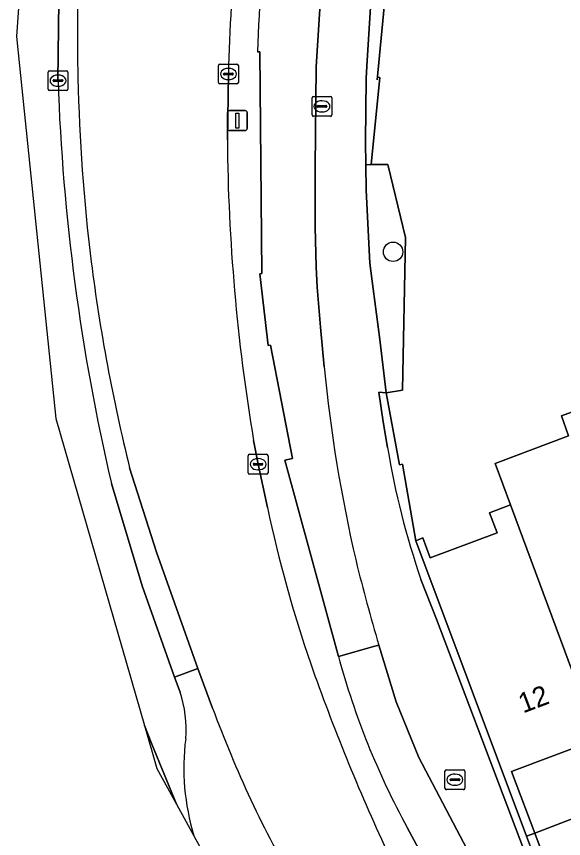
# Model space of a CAD drawing. Extents: x 160663 to 161506, y 382245 to 383291.
# Drawn here: x 160662.59 to 160690.09, y 383134.14 to 383175.45 of the extents above; entities that cross this region are included whole.
import ezdxf

# ---------------------------------------------------------------- set-up
doc = ezdxf.new("R2010")
doc.units = 0
for name, color, linetype in [('IMGEO_Berm_gesloten', 7, 'Continuous'), ('IMGEO_Berm_open', 7, 'Continuous'), ('IMGEO_Boom', 7, 'Continuous'), ('IMGEO_Erf', 7, 'Continuous'), ('IMGEO_Fietspad_gesloten', 7, 'Continuous'), ('IMGEO_Fietspad_open', 7, 'Continuous'), ('IMGEO_Groenvoorziening', 7, 'Continuous'), ('IMGEO_Haag', 7, 'Continuous'), ('IMGEO_Kolk', 7, 'Continuous'), ('IMGEO_Lichtmast', 7, 'Continuous'), ('IMGEO_Muur', 7, 'Continuous'), ('IMGEO_Pand', 7, 'Continuous'), ('IMGEO_Pand_nummerreeks', 7, 'Continuous'), ('IMGEO_Pand_overbouw', 7, 'Continuous'), ('IMGEO_Rijbaan_lokaal_gesloten', 7, 'Continuous'), ('IMGEO_Rioolput', 7, 'Continuous'), ('IMGEO_Voetpad_open', 7, 'Continuous')]:
    doc.layers.add(name, color=color, linetype=linetype)

msp = doc.modelspace()

# ---------------------------------------------------------------- linework, layer by layer
at = {"layer": 'IMGEO_Berm_gesloten'}
for points in [[(160665.999, 383192.975), (160665.276, 383186.827), (160664.748, 383178.894), (160664.679, 383172.227)], [(160667.367, 383151.979), (160668.909, 383146.839), (160670.541, 383142.243), (160671.716, 383142.678), (160669.629, 383148.526), (160668.281, 383152.765)]]:
    msp.add_lwpolyline(points, dxfattribs=at)
for centre, radius, start, end in [((160766.24, 383174.55), 100.581, 160.36227, 181.25641), ((160754.17, 383174.111), 88.504, 181.14338, 187.13117), ((160769.093, 383175.786), 104.474, 181.95215, 193.17189), ((160754.088, 383174.12), 88.424, 187.14324, 193.97516)]:
    msp.add_arc(centre, radius, start, end, dxfattribs=at)
at = {"layer": 'IMGEO_Berm_open'}
for points in [[(160676.079, 383153.149), (160676.474, 383153.238), (160675.361, 383158.93), (160675.236, 383158.916), (160674.821, 383162.521), (160674.928, 383162.528), (160674.82, 383173.67), (160674.699, 383173.666)], [(160673.244, 383172.558), (160673.191, 383169.258)], [(160674.508, 383154.138), (160674.736, 383152.95), (160675.211, 383150.768)], [(160678.773, 383143.293), (160676.079, 383153.149)], [(160686.25, 383127.523), (160683.772, 383131.833), (160682.228, 383134.688)]]:
    msp.add_lwpolyline(points, dxfattribs=at)
for centre, radius, start, end in [((160749.666, 383171.084), 76.436, 168.75951, 178.89467), ((160756.054, 383170.693), 81.409, 172.7867, 177.90714), ((160770.077, 383170.08), 96.889, 180.48592, 189.47024), ((160739.82, 383164.449), 66.042, 191.95555, 199.0226), ((160717.456, 383153.829), 40.092, 195.2353, 208.5166), ((160774.65, 383176.997), 103.061, 199.30669, 204.94851)]:
    msp.add_arc(centre, radius, start, end, dxfattribs=at)
at = {"layer": 'IMGEO_Boom'}
msp.add_circle((160681.522, 383163.624), 0.489, dxfattribs=at)
at = {"layer": 'IMGEO_Erf'}
msp.add_lwpolyline([(160681.165, 383176.816), (160680.714, 383172.272), (160680.732, 383172.404), (160680.853, 383172.385), (160680.413, 383168.005), (160681.264, 383168.017), (160682.139, 383164.35), (160681.99, 383156.668), (160681.179, 383156.533), (160681.848, 383152.917), (160681.993, 383152.948), (160682.661, 383149.105), (160683.014, 383149.243), (160683.39, 383148.241), (160686.746, 383149.5), (160686.367, 383150.501), (160687.427, 383150.902), (160686.655, 383152.982), (160690.339, 383154.37), (160689.98, 383155.388), (160691.046, 383155.764)], dxfattribs=at)
at = {"layer": 'IMGEO_Fietspad_gesloten'}
for points in [[(160693.798, 383117.07), (160693.112, 383118.673), (160689.259, 383126.716), (160688.071, 383128.53), (160685.926, 383132.285), (160682.818, 383138.215), (160681.684, 383141.007), (160680.807, 383143.865), (160680.607, 383143.809), (160678.773, 383143.293)], [(160682.228, 383134.688), (160683.772, 383131.833), (160686.25, 383127.523), (160688.317, 383124.05), (160688.871, 383123.049)]]:
    msp.add_lwpolyline(points, dxfattribs=at)
msp.add_arc((160717.456, 383153.829), 40.092, 195.2353, 208.5166, dxfattribs=at)
at = {"layer": 'IMGEO_Fietspad_open'}
for points in [[(160678.062, 383157.847), (160677.872, 383159.844), (160677.706, 383161.844), (160677.655, 383162.864), (160677.604, 383164.862), (160677.598, 383167.868), (160677.66, 383172.913), (160677.907, 383176.899)], [(160674.699, 383173.666), (160674.82, 383173.67), (160674.928, 383162.528), (160674.821, 383162.521), (160675.236, 383158.916), (160675.361, 383158.93), (160676.474, 383153.238), (160676.079, 383153.149), (160678.773, 383143.293), (160680.607, 383143.809), (160680.807, 383143.865)]]:
    msp.add_lwpolyline(points, dxfattribs=at)
for centre, radius, start, end in [((160756.054, 383170.693), 81.409, 172.7867, 177.90714), ((160752.54, 383165.023), 74.822, 185.50344, 193.08214), ((160765.977, 383169.29), 88.884, 193.80114, 196.62181)]:
    msp.add_arc(centre, radius, start, end, dxfattribs=at)
at = {"layer": 'IMGEO_Groenvoorziening'}
for points in [[(160680.413, 383176.477), (160680.208, 383172.951), (160680.177, 383172.339), (160680.133, 383169.162), (160680.153, 383168.001), (160680.413, 383168.005), (160680.853, 383172.385), (160680.732, 383172.404), (160680.714, 383172.272), (160681.165, 383176.816)], [(160694.878, 383127.414), (160694.597, 383127.794), (160694.687, 383127.874), (160694.639, 383127.986), (160694.165, 383127.567), (160693.585, 383126.77), (160693.086, 383126.386), (160692.418, 383126.118), (160691.581, 383126.061), (160689.892, 383130.523), (160689.656, 383130.434), (160689.45, 383130.983), (160688.877, 383132.514), (160688.225, 383134.254), (160682.661, 383149.105), (160681.993, 383152.948), (160681.848, 383152.917), (160681.179, 383156.533), (160680.804, 383156.569), (160681.025, 383155.081), (160681.247, 383153.783)], [(160682.924, 383147.162), (160683.705, 383145.169), (160689.33, 383130.312), (160690.049, 383128.413), (160691.131, 383125.556)], [(160672.451, 383140.698), (160671.716, 383142.678), (160670.541, 383142.243), (160670.815, 383141.499)], [(160692.952, 383133.223), (160692.787, 383135.987), (160690.388, 383135.074), (160688.645, 383134.411), (160689.325, 383132.618), (160689.862, 383131.202), (160690.091, 383130.597), (160689.892, 383130.523), (160691.581, 383126.061), (160692.418, 383126.118), (160693.086, 383126.386), (160693.585, 383126.77), (160694.165, 383127.567), (160694.639, 383127.986), (160693.626, 383130.337)], [(160671.51, 383134.28), (160674.846, 383128.19)]]:
    msp.add_lwpolyline(points, dxfattribs=at)
msp.add_lwpolyline([(160681.179, 383156.533), (160681.99, 383156.668), (160682.139, 383164.35), (160681.264, 383168.017), (160680.413, 383168.005), (160680.153, 383168.001), (160680.176, 383166.719), (160680.355, 383163.046), (160680.525, 383161.77), (160680.849, 383159.223)], close=True, dxfattribs=at)
for centre, radius, start, end in [((160721.286, 383160.401), 40.582, 189.386, 199.0405), ((160665.192, 383139.633), 5.925, 355.3599, 18.3545), ((160727.086, 383160.771), 58.205, 200.17318, 210.00906), ((160682.695, 383137.682), 11.691, 172.7671, 196.9178)]:
    msp.add_arc(centre, radius, start, end, dxfattribs=at)
at = {"layer": 'IMGEO_Haag'}
for points in [[(160680.413, 383176.477), (160680.208, 383172.951), (160680.177, 383172.339), (160680.133, 383169.162), (160680.153, 383168.001), (160680.413, 383168.005), (160680.853, 383172.385), (160680.732, 383172.404), (160680.714, 383172.272), (160681.165, 383176.816)], [(160694.878, 383127.414), (160694.597, 383127.794), (160694.687, 383127.874), (160694.639, 383127.986), (160694.165, 383127.567), (160693.585, 383126.77), (160693.086, 383126.386), (160692.418, 383126.118), (160691.581, 383126.061), (160689.892, 383130.523), (160689.656, 383130.434), (160689.45, 383130.983), (160688.877, 383132.514), (160688.225, 383134.254), (160682.661, 383149.105), (160681.993, 383152.948), (160681.848, 383152.917), (160681.179, 383156.533), (160680.804, 383156.569), (160681.025, 383155.081), (160681.247, 383153.783)], [(160682.924, 383147.162), (160683.705, 383145.169), (160689.33, 383130.312), (160690.049, 383128.413), (160691.131, 383125.556)]]:
    msp.add_lwpolyline(points, dxfattribs=at)
msp.add_arc((160721.286, 383160.401), 40.582, 189.386, 199.0405, dxfattribs=at)
at = {"layer": 'IMGEO_Kolk'}
for p, q in [((160664.255, 383172.724), (160665.107, 383172.724)), ((160672.744, 383172.132), (160672.744, 383172.984)), ((160672.819, 383173.058), (160673.671, 383173.058)), ((160673.232, 383172.838), (160673.257, 383172.838)), ((160673.745, 383172.984), (160673.745, 383172.132)), ((160664.18, 383171.798), (160664.18, 383172.65)), ((160664.482, 383172.267), (160664.88, 383172.267)), ((160664.668, 383172.504), (160664.693, 383172.504)), ((160665.181, 383172.65), (160665.181, 383171.798)), ((160673.003, 383172.552), (160673.003, 383172.564)), ((160673.441, 383172.515), (160673.043, 383172.515)), ((160673.046, 383172.601), (160673.444, 383172.601)), ((160673.255, 383172.278), (160673.23, 383172.278)), ((160673.487, 383172.564), (160673.487, 383172.552)), ((160664.439, 383172.218), (160664.439, 383172.23)), ((160664.877, 383172.181), (160664.479, 383172.181)), ((160664.691, 383171.944), (160664.666, 383171.944)), ((160664.923, 383172.23), (160664.923, 383172.218)), ((160673.671, 383172.058), (160672.819, 383172.058)), ((160665.107, 383171.724), (160664.255, 383171.724)), ((160674.236, 383152.525), (160674.236, 383153.377)), ((160674.311, 383153.451), (160675.163, 383153.451)), ((160675.237, 383153.377), (160675.237, 383152.525)), ((160674.495, 383152.945), (160674.495, 383152.957)), ((160674.933, 383152.908), (160674.535, 383152.908)), ((160674.538, 383152.994), (160674.936, 383152.994)), ((160674.724, 383153.231), (160674.749, 383153.231)), ((160674.979, 383152.957), (160674.979, 383152.945)), ((160675.163, 383152.451), (160674.311, 383152.451)), ((160674.747, 383152.671), (160674.722, 383152.671))]:
    msp.add_line(p, q, dxfattribs=at)
for points in [[(160664.255, 383172.724), (160665.107, 383172.724)], [(160672.744, 383172.132), (160672.744, 383172.984)], [(160672.819, 383173.058), (160673.671, 383173.058)], [(160673.745, 383172.984), (160673.745, 383172.132)], [(160664.18, 383171.798), (160664.18, 383172.65)], [(160665.181, 383172.65), (160665.181, 383171.798)], [(160673.671, 383172.058), (160672.819, 383172.058)], [(160665.107, 383171.724), (160664.255, 383171.724)], [(160674.236, 383152.525), (160674.236, 383153.377)], [(160674.311, 383153.451), (160675.163, 383153.451)], [(160675.237, 383153.377), (160675.237, 383152.525)], [(160675.163, 383152.451), (160674.311, 383152.451)]]:
    msp.add_lwpolyline(points, dxfattribs=at)
for centre, radius, start, end in [((160664.257, 383172.648), 0.0765, 91.552, 178.448), ((160664.257, 383172.648), 0.0765, 91.552, 178.448), ((160665.105, 383172.648), 0.0765, 1.552, 88.448), ((160665.105, 383172.648), 0.0765, 1.552, 88.448), ((160672.821, 383172.982), 0.0765, 91.552, 178.448), ((160672.821, 383172.982), 0.0765, 91.552, 178.448), ((160673.669, 383172.982), 0.0765, 1.552, 88.448), ((160673.669, 383172.982), 0.0765, 1.552, 88.448), ((160664.479, 383172.227), 0.0403, 85.8775, 175.7526), ((160664.884, 383172.229), 0.0386, 1.7309, 96.639), ((160673.043, 383172.561), 0.0403, 85.8775, 175.7526), ((160673.04, 383172.551), 0.0366, 178.938, 274.7102), ((160673.444, 383172.558), 0.043, 264.8664, 352.4533), ((160673.448, 383172.563), 0.0386, 1.7309, 96.639), ((160664.476, 383172.217), 0.0366, 178.938, 274.7102), ((160664.88, 383172.224), 0.043, 264.8664, 352.4533), ((160672.821, 383172.134), 0.0765, 181.552, 268.448), ((160672.821, 383172.134), 0.0765, 181.552, 268.448), ((160673.669, 383172.134), 0.0765, 271.552, 358.448), ((160673.669, 383172.134), 0.0765, 271.552, 358.448), ((160664.257, 383171.8), 0.0765, 181.552, 268.448), ((160664.257, 383171.8), 0.0765, 181.552, 268.448), ((160665.105, 383171.8), 0.0765, 271.552, 358.448), ((160665.105, 383171.8), 0.0765, 271.552, 358.448), ((160674.313, 383153.375), 0.0765, 91.552, 178.448), ((160674.313, 383153.375), 0.0765, 91.552, 178.448), ((160675.161, 383153.375), 0.0765, 1.552, 88.448), ((160675.161, 383153.375), 0.0765, 1.552, 88.448), ((160674.535, 383152.954), 0.0403, 85.8775, 175.7526), ((160674.532, 383152.944), 0.0366, 178.938, 274.7102), ((160674.936, 383152.951), 0.043, 264.8664, 352.4533), ((160674.94, 383152.956), 0.0386, 1.7309, 96.639), ((160674.313, 383152.527), 0.0765, 181.552, 268.448), ((160674.313, 383152.527), 0.0765, 181.552, 268.448), ((160675.161, 383152.527), 0.0765, 271.552, 358.448), ((160675.161, 383152.527), 0.0765, 271.552, 358.448)]:
    msp.add_arc(centre, radius, start, end, dxfattribs=at)
for centre, major_axis, ratio, start_param, end_param in [((160673.231, 383172.558), (-0.387, 0.002), 0.722429, 4.712389, 7.853982), ((160673.256, 383172.558), (-0.39, 0.002), 0.717154, 1.570796, 4.712389), ((160664.667, 383172.224), (-0.387, 0.002), 0.722429, 4.712389, 7.853982), ((160664.692, 383172.224), (-0.39, 0.002), 0.717154, 1.570796, 4.712389), ((160674.723, 383152.951), (-0.387, 0.002), 0.722429, 4.712389, 7.853982), ((160674.748, 383152.951), (-0.39, 0.002), 0.717154, 1.570796, 4.712389)]:
    msp.add_ellipse(centre, major_axis=major_axis, ratio=ratio, start_param=start_param, end_param=end_param, dxfattribs=at)
at = {"layer": 'IMGEO_Lichtmast'}
for p, q in [((160673.199, 383169.819), (160673.199, 383170.619)), ((160673.199, 383170.619), (160673.199, 383169.819)), ((160673.299, 383170.719), (160674.089, 383170.719)), ((160674.089, 383170.719), (160673.299, 383170.719)), ((160674.189, 383170.619), (160674.189, 383169.819)), ((160674.189, 383169.819), (160674.189, 383170.619)), ((160674.089, 383169.719), (160673.299, 383169.719)), ((160673.299, 383169.719), (160674.089, 383169.719))]:
    msp.add_line(p, q, dxfattribs=at)
msp.add_lwpolyline([(160673.619, 383170.594), (160673.769, 383170.594), (160673.769, 383169.844), (160673.619, 383169.844), (160673.619, 383170.594)], dxfattribs=at)
for centre, start, end in [((160673.299, 383170.619), 90, 180), ((160673.299, 383170.619), 90, 180), ((160674.089, 383170.619), 0, 90), ((160674.089, 383170.619), 360, 90), ((160673.299, 383169.819), 180, 270), ((160673.299, 383169.819), 180, 270), ((160674.089, 383169.819), 270, 0), ((160674.089, 383169.819), 270, 0)]:
    msp.add_arc(centre, 0.1, start, end, dxfattribs=at)
at = {"layer": 'IMGEO_Muur'}
msp.add_lwpolyline([(160687.718, 383202.423), (160686.074, 383198.261), (160686.135, 383198.38), (160686.238, 383198.331), (160684.578, 383194.06), (160684.637, 383194.186), (160684.746, 383194.124), (160683.252, 383189.796), (160683.308, 383189.923), (160683.42, 383189.871), (160682.202, 383185.493), (160682.257, 383185.625), (160682.375, 383185.575), (160681.483, 383181.119), (160681.526, 383181.232), (160681.646, 383181.19), (160681.02, 383176.711), (160681.047, 383176.835), (160681.165, 383176.816), (160680.714, 383172.272), (160680.732, 383172.404), (160680.853, 383172.385), (160680.413, 383168.005)], dxfattribs=at)
msp.add_lwpolyline([(160689.862, 383131.202), (160689.325, 383132.618), (160688.645, 383134.411), (160688.225, 383134.254), (160688.877, 383132.514), (160689.45, 383130.983), (160689.656, 383130.434), (160689.892, 383130.523), (160690.091, 383130.597)], close=True, dxfattribs=at)
at = {"layer": 'IMGEO_Pand'}
for points in [[(160691.046, 383155.764), (160689.98, 383155.388), (160690.339, 383154.37), (160686.655, 383152.982), (160687.427, 383150.902), (160691.792, 383139.141), (160692.254, 383139.315), (160692.879, 383139.558), (160692.756, 383139.873), (160692.123, 383139.625), (160691.087, 383142.408), (160695.406, 383144.016)], [(160687.427, 383150.902), (160686.367, 383150.501), (160686.746, 383149.5), (160683.39, 383148.241), (160683.014, 383149.243), (160682.661, 383149.105), (160688.225, 383134.254), (160688.645, 383134.411), (160687.478, 383137.512), (160691.792, 383139.141)]]:
    msp.add_lwpolyline(points, close=True, dxfattribs=at)
at = {"layer": 'IMGEO_Pand_overbouw'}
msp.add_lwpolyline([(160692.672, 383138.199), (160692.254, 383139.315), (160691.792, 383139.141), (160687.478, 383137.512), (160688.645, 383134.411), (160690.388, 383135.074), (160692.787, 383135.987), (160693.411, 383136.224)], close=True, dxfattribs=at)
at = {"layer": 'IMGEO_Rijbaan_lokaal_gesloten'}
for points in [[(160687.72, 383258.106), (160688.057, 383259.324), (160689.344, 383264.684), (160688.005, 383264.811), (160677.782, 383230.912), (160664.085, 383195.806), (160662.59, 383174.443), (160662.741, 383172.971), (160664.567, 383155.247), (160669.029, 383139.828), (160669.397, 383138.878), (160670.641, 383135.865), (160671.51, 383134.28)], [(160664.679, 383172.227), (160664.748, 383178.894), (160665.276, 383186.827), (160665.999, 383192.975)], [(160673.191, 383169.258), (160673.244, 383172.558)], [(160675.211, 383150.768), (160674.736, 383152.95), (160674.508, 383154.138)], [(160668.281, 383152.765), (160669.629, 383148.526), (160671.716, 383142.678), (160672.451, 383140.698)], [(160670.815, 383141.499), (160670.541, 383142.243), (160668.909, 383146.839), (160667.367, 383151.979)], [(160669.029, 383139.828), (160669.655, 383137.666), (160670.641, 383135.865), (160669.397, 383138.878), (160669.029, 383139.828)]]:
    msp.add_lwpolyline(points, dxfattribs=at)
for centre, radius, start, end in [((160766.24, 383174.55), 100.581, 160.36227, 181.25641), ((160749.666, 383171.084), 76.436, 168.75951, 178.89467), ((160754.17, 383174.111), 88.504, 181.14338, 187.13117), ((160769.093, 383175.786), 104.474, 181.95215, 193.17189), ((160770.077, 383170.08), 96.889, 180.48592, 189.47024), ((160754.088, 383174.12), 88.424, 187.14324, 193.97516), ((160739.82, 383164.449), 66.042, 191.95555, 199.0226), ((160774.65, 383176.997), 103.061, 199.30669, 204.94851), ((160665.192, 383139.633), 5.925, 355.3599, 18.3545), ((160727.086, 383160.771), 58.205, 200.17318, 210.00906), ((160682.695, 383137.682), 11.691, 172.7671, 196.9178)]:
    msp.add_arc(centre, radius, start, end, dxfattribs=at)
at = {"layer": 'IMGEO_Rioolput'}
for p, q in [((160677.522, 383171.431), (160678.374, 383171.431)), ((160677.447, 383170.505), (160677.447, 383171.357)), ((160677.935, 383171.211), (160677.96, 383171.211)), ((160678.448, 383171.357), (160678.448, 383170.505)), ((160677.706, 383170.925), (160677.706, 383170.937)), ((160678.144, 383170.888), (160677.746, 383170.888)), ((160677.749, 383170.974), (160678.147, 383170.974)), ((160677.958, 383170.651), (160677.933, 383170.651)), ((160678.19, 383170.937), (160678.19, 383170.925)), ((160678.374, 383170.431), (160677.522, 383170.431)), ((160684.205, 383137.597), (160685.057, 383137.597)), ((160684.13, 383136.671), (160684.13, 383137.523)), ((160684.618, 383137.377), (160684.643, 383137.377)), ((160685.131, 383137.523), (160685.131, 383136.671)), ((160684.389, 383137.091), (160684.389, 383137.103)), ((160684.827, 383137.054), (160684.429, 383137.054)), ((160684.432, 383137.14), (160684.83, 383137.14)), ((160684.641, 383136.817), (160684.616, 383136.817)), ((160684.873, 383137.103), (160684.873, 383137.091)), ((160685.057, 383136.597), (160684.205, 383136.597))]:
    msp.add_line(p, q, dxfattribs=at)
for points in [[(160677.522, 383171.431), (160678.374, 383171.431)], [(160677.447, 383170.505), (160677.447, 383171.357)], [(160678.448, 383171.357), (160678.448, 383170.505)], [(160678.374, 383170.431), (160677.522, 383170.431)], [(160684.205, 383137.597), (160685.057, 383137.597)], [(160684.13, 383136.671), (160684.13, 383137.523)], [(160685.131, 383137.523), (160685.131, 383136.671)], [(160685.057, 383136.597), (160684.205, 383136.597)]]:
    msp.add_lwpolyline(points, dxfattribs=at)
for centre, radius, start, end in [((160677.524, 383171.355), 0.0765, 91.552, 178.448), ((160677.524, 383171.355), 0.0765, 91.552, 178.448), ((160678.372, 383171.355), 0.0765, 1.552, 88.448), ((160678.372, 383171.355), 0.0765, 1.552, 88.448), ((160677.746, 383170.934), 0.0403, 85.8775, 175.7526), ((160677.743, 383170.924), 0.0366, 178.938, 274.7102), ((160678.147, 383170.931), 0.043, 264.8664, 352.4533), ((160678.151, 383170.936), 0.0386, 1.7309, 96.639), ((160677.524, 383170.507), 0.0765, 181.552, 268.448), ((160677.524, 383170.507), 0.0765, 181.552, 268.448), ((160678.372, 383170.507), 0.0765, 271.552, 358.448), ((160678.372, 383170.507), 0.0765, 271.552, 358.448), ((160684.207, 383137.521), 0.0765, 91.552, 178.448), ((160684.207, 383137.521), 0.0765, 91.552, 178.448), ((160685.055, 383137.521), 0.0765, 1.552, 88.448), ((160685.055, 383137.521), 0.0765, 1.552, 88.448), ((160684.429, 383137.1), 0.0403, 85.8775, 175.7526), ((160684.426, 383137.09), 0.0366, 178.938, 274.7102), ((160684.83, 383137.097), 0.043, 264.8664, 352.4533), ((160684.834, 383137.102), 0.0386, 1.7309, 96.639), ((160684.207, 383136.673), 0.0765, 181.552, 268.448), ((160684.207, 383136.673), 0.0765, 181.552, 268.448), ((160685.055, 383136.673), 0.0765, 271.552, 358.448), ((160685.055, 383136.673), 0.0765, 271.552, 358.448)]:
    msp.add_arc(centre, radius, start, end, dxfattribs=at)
for centre, major_axis, ratio, start_param, end_param in [((160677.934, 383170.931), (-0.387, 0.002), 0.722429, 4.712389, 7.853982), ((160677.959, 383170.931), (-0.39, 0.002), 0.717154, 1.570796, 4.712389), ((160684.617, 383137.097), (-0.387, 0.002), 0.722429, 4.712389, 7.853982), ((160684.642, 383137.097), (-0.39, 0.002), 0.717154, 1.570796, 4.712389)]:
    msp.add_ellipse(centre, major_axis=major_axis, ratio=ratio, start_param=start_param, end_param=end_param, dxfattribs=at)
at = {"layer": 'IMGEO_Voetpad_open'}
for points in [[(160681.247, 383153.783), (160681.025, 383155.081), (160680.804, 383156.569), (160681.179, 383156.533), (160680.849, 383159.223), (160680.525, 383161.77), (160680.355, 383163.046), (160680.176, 383166.719), (160680.153, 383168.001), (160680.133, 383169.162), (160680.177, 383172.339), (160680.208, 383172.951), (160680.413, 383176.477), (160680.584, 383178.639), (160681.149, 383182.722), (160681.192, 383182.923)], [(160677.907, 383176.899), (160677.66, 383172.913), (160677.598, 383167.868), (160677.604, 383164.862), (160677.655, 383162.864), (160677.706, 383161.844), (160677.872, 383159.844), (160678.062, 383157.847)], [(160691.131, 383125.556), (160690.049, 383128.413), (160689.33, 383130.312), (160683.705, 383145.169), (160682.924, 383147.162)], [(160680.807, 383143.865), (160681.684, 383141.007), (160682.818, 383138.215), (160685.926, 383132.285), (160688.071, 383128.53), (160689.259, 383126.716)]]:
    msp.add_lwpolyline(points, dxfattribs=at)
msp.add_lwpolyline([(160692.672, 383138.199), (160692.254, 383139.315), (160691.792, 383139.141), (160687.478, 383137.512), (160688.645, 383134.411), (160690.388, 383135.074), (160692.787, 383135.987), (160693.411, 383136.224)], close=True, dxfattribs=at)
for centre, radius, start, end in [((160752.54, 383165.023), 74.822, 185.50344, 193.08214), ((160721.286, 383160.401), 40.582, 189.386, 199.0405), ((160765.977, 383169.29), 88.884, 193.80114, 196.62181)]:
    msp.add_arc(centre, radius, start, end, dxfattribs=at)

# ---------------------------------------------------------------- texts
at = {"layer": 'IMGEO_Pand_nummerreeks'}
msp.add_text('12', height=1, rotation=20.6822, dxfattribs=at).set_placement((160688.055, 383140.423))

doc.saveas('drawing.dxf')
